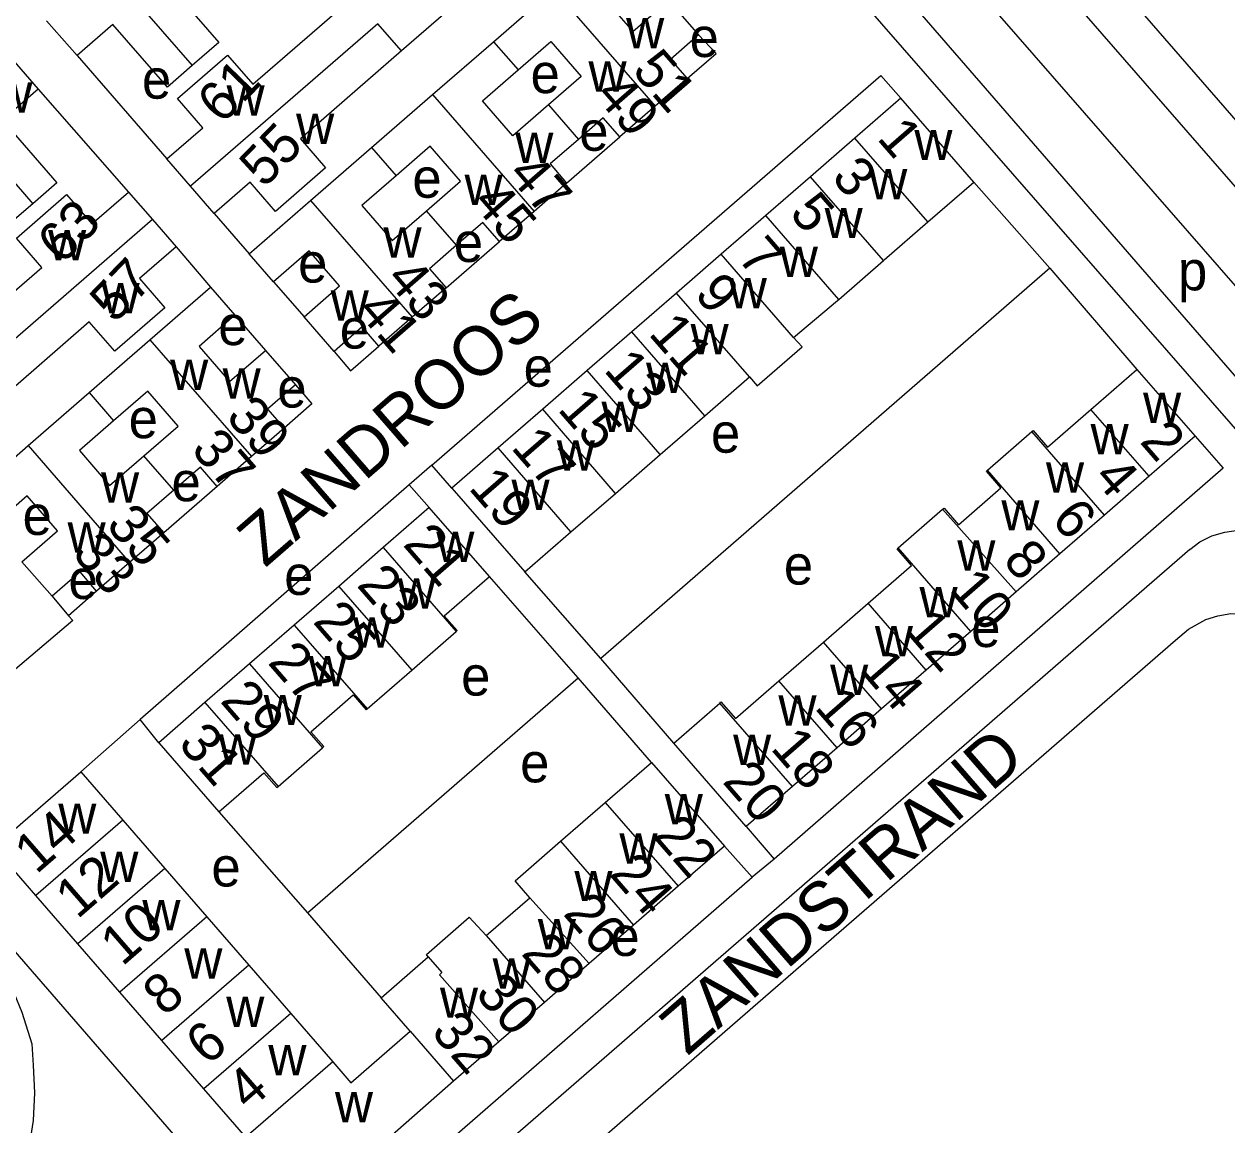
# Model space of a CAD drawing. Extents: x 155854 to 157362, y 383621 to 384685.
# Drawn here: x 156376.4 to 156498.5, y 383977 to 384088.8 of the extents above; entities that cross this region are included whole.
import ezdxf

# ---------------------------------------------------------------- set-up
doc = ezdxf.new("R2010")
doc.units = 0
for name, color, linetype in [('BLT_Basislijn', 7, 'Continuous'), ('BLT_Bebouwing', 7, 'Continuous'), ('BLT_Centroide', 7, 'Continuous'), ('BLT_Huisnummer', 7, 'Continuous'), ('BLT_Huisnummer_ tussenligend', 7, 'Continuous'), ('BLT_Onderverdeling_panden', 7, 'Continuous'), ('BLT_Straatnaam', 7, 'Continuous')]:
    doc.layers.add(name, color=color, linetype=linetype)

msp = doc.modelspace()

# ---------------------------------------------------------------- linework, layer by layer
at = {"layer": 'BLT_Basislijn'}
for p, q in [((156392.09, 384202.53), (156523.62, 384051.13)), ((156401.6, 384165.8), (156512.2, 384038.19)), ((156398.58, 384163.18), (156509.58, 384035.97)), ((156520.26, 384048.21), (156473.56, 384101.96)), ((156516.87, 384042.15), (156471.07, 384094.69)), ((156446.65, 384085.79), (156444.87, 384087.69)), ((156381.78, 384085.6), (156390.89, 384075.11)), ((156443.7, 384083.27), (156446.65, 384085.79)), ((156417.79, 384044.01), (156463.38, 384083.58)), ((156463.38, 384083.58), (156465.4, 384081.27)), ((156377.85, 384082.2), (156387.01, 384071.73)), ((156431.48, 384072.64), (156436.88, 384077.35)), ((156472.82, 384072.75), (156480.52, 384064)), ((156395.69, 384069.56), (156399.27, 384065.48)), ((156419.24, 384062.02), (156424.65, 384066.71)), ((156391.83, 384066.18), (156395.32, 384062.09)), ((156480.52, 384064), (156434.94, 384024.4)), ((156480.52, 384064), (156489.37, 384053.73)), ((156401.74, 384062.62), (156404.82, 384059.07)), ((156397.81, 384059.23), (156400.91, 384055.67)), ((156407.87, 384055.55), (156409.55, 384053.58)), ((156409.55, 384053.58), (156412.43, 384056.11)), ((156403.95, 384052.17), (156405.63, 384050.24)), ((156405.63, 384050.24), (156402.79, 384047.77)), ((156495.29, 384046.95), (156498.14, 384043.71)), ((156417.79, 384044.01), (156415.51, 384042.01)), ((156419.83, 384041.68), (156417.79, 384044.01)), ((156498.14, 384043.71), (156452.55, 384004.01)), ((156415.51, 384042.01), (156388.19, 384018.19)), ((156417.54, 384039.71), (156415.51, 384042.01)), ((156395.99, 384041.86), (156390.58, 384037.15)), ((156494.73, 384035.45), (156450.99, 383997.45)), ((156432.65, 384022.41), (156423.64, 384032.71)), ((156434.94, 384024.4), (156427.24, 384033.18)), ((156383.77, 384031.23), (156380.92, 384028.72)), ((156379.24, 384030.7), (156380.92, 384028.72)), ((156380.92, 384028.72), (156381.34, 384028.23)), ((156381.34, 384028.23), (156374.19, 384022.15)), ((156448.33, 383987.19), (156493.28, 384026.24)), ((156442.36, 384015.8), (156434.94, 384024.4)), ((156405.18, 383998.55), (156432.65, 384022.41)), ((156440.08, 384013.84), (156432.65, 384022.41)), ((156388.19, 384018.19), (156382.16, 384012.89)), ((156390.09, 384015.84), (156388.19, 384018.19)), ((156396.19, 384008.82), (156405.18, 383998.55)), ((156449.72, 384007.32), (156452.55, 384004.01)), ((156447.49, 384005.33), (156450.33, 384002.17)), ((156452.55, 384004.01), (156450.33, 384002.17)), ((156369.3, 384001.72), (156403.93, 383961.86)), ((156403.93, 383961.86), (156450.33, 384002.17)), ((156405.18, 383998.55), (156412.64, 383989.95)), ((156404.62, 383949.22), (156448.33, 383987.19))]:
    msp.add_line(p, q, dxfattribs=at)
for points in [[(156494.73, 384035.45), (156495.76, 384036.23), (156496.98, 384036.84), (156498.28, 384037.22), (156499.89, 384037.45), (156500.8, 384037.38), (156501.87, 384037.15), (156503.02, 384036.84), (156504.02, 384036.3), (156505.16, 384035.46), (156506.01, 384034.65), (156506.74, 384033.82)], [(156493.28, 384026.24), (156494.61, 384027.36), (156496.37, 384028.35), (156497.59, 384028.73), (156498.89, 384028.96), (156500.27, 384028.89), (156501.57, 384028.66), (156502.33, 384028.35), (156502.88, 384028.08)], [(156369.3, 384001.72), (156368.39, 383999.97), (156370.56, 383997.41), (156372.6, 383994.73), (156374.65, 383992.04), (156375.41, 383990.38), (156376.18, 383988.47), (156377.2, 383985.27), (156377.33, 383983.1), (156377.46, 383980.29), (156377.33, 383977.47), (156376.69, 383973.38), (156375.92, 383967.54), (156378.01, 383961.92)], [(156450.99, 383997.45), (156407.25, 383959.46), (156405.53, 383958.27)]]:
    msp.add_lwpolyline(points, dxfattribs=at)
at = {"layer": 'BLT_Bebouwing'}
for p, q in [((156424.06, 384087), (156430.17, 384092.31)), ((156441.83, 384091.18), (156444.87, 384087.69)), ((156381.78, 384085.6), (156378.69, 384089.13)), ((156417.87, 384081.63), (156424.06, 384087)), ((156426.55, 384084.14), (156429.87, 384087.03)), ((156374.77, 384085.74), (156377.85, 384082.2)), ((156443.7, 384083.27), (156440.47, 384080.46)), ((156411.68, 384076.26), (156417.87, 384081.63)), ((156465.4, 384081.27), (156460.74, 384077.22)), ((156472.82, 384072.75), (156465.4, 384081.27)), ((156440.47, 384080.46), (156436.88, 384077.35)), ((156405.49, 384070.88), (156411.68, 384076.26)), ((156417.64, 384076.39), (156414.17, 384073.39)), ((156460.74, 384077.22), (156456.23, 384073.3)), ((156393.3, 384072.32), (156390.89, 384075.11)), ((156431.48, 384072.64), (156428.17, 384069.77)), ((156456.23, 384073.3), (156451.69, 384069.36)), ((156387.01, 384071.73), (156389.43, 384068.95)), ((156395.69, 384069.56), (156393.3, 384072.32)), ((156399.27, 384065.48), (156405.49, 384070.88)), ((156389.43, 384068.95), (156391.83, 384066.18)), ((156428.17, 384069.77), (156424.65, 384066.71)), ((156451.69, 384069.36), (156447.16, 384065.42)), ((156463.73, 384064.86), (156468.16, 384068.7)), ((156401.74, 384062.62), (156399.27, 384065.48)), ((156447.16, 384065.42), (156442.63, 384061.49)), ((156459.1, 384060.84), (156463.64, 384064.78)), ((156463.64, 384064.78), (156463.73, 384064.86)), ((156389.18, 384056.75), (156395.32, 384062.09)), ((156395.32, 384062.09), (156397.81, 384059.23)), ((156419.24, 384062.02), (156415.79, 384059.03)), ((156442.63, 384061.49), (156438.1, 384057.56)), ((156454.5, 384056.97), (156458.98, 384060.73)), ((156458.98, 384060.73), (156459.1, 384060.84)), ((156407.87, 384055.55), (156404.82, 384059.07)), ((156415.79, 384059.03), (156412.43, 384056.11)), ((156383, 384051.38), (156389.18, 384056.75)), ((156438.1, 384057.56), (156433.58, 384053.62)), ((156400.91, 384055.67), (156403.95, 384052.17)), ((156433.58, 384053.62), (156429.05, 384049.69)), ((156484.71, 384049.68), (156489.37, 384053.73)), ((156489.37, 384053.73), (156495.29, 384046.95)), ((156445.5, 384049.03), (156450.04, 384052.97)), ((156376.81, 384046), (156383, 384051.38)), ((156388.96, 384051.53), (156385.48, 384048.52)), ((156429.05, 384049.69), (156424.52, 384045.76)), ((156440.97, 384045.1), (156445.5, 384049.03)), ((156402.79, 384047.77), (156399.48, 384044.89)), ((156474.2, 384043.49), (156478.72, 384047.42)), ((156478.72, 384047.42), (156478.84, 384047.53)), ((156495.29, 384046.95), (156490.61, 384042.88)), ((156370.62, 384040.61), (156376.81, 384046)), ((156424.52, 384045.76), (156419.83, 384041.68)), ((156399.48, 384044.89), (156395.99, 384041.86)), ((156436.45, 384041.15), (156440.97, 384045.1)), ((156474.09, 384043.4), (156474.2, 384043.49)), ((156490.61, 384042.88), (156486.09, 384038.95)), ((156419.83, 384041.68), (156427.24, 384033.18)), ((156431.91, 384037.23), (156436.45, 384041.15)), ((156417.54, 384039.71), (156412.87, 384035.65)), ((156423.64, 384032.71), (156417.54, 384039.71)), ((156469.65, 384039.53), (156469.79, 384039.66)), ((156465.15, 384035.62), (156469.65, 384039.53)), ((156486.09, 384038.95), (156481.56, 384035.01)), ((156390.58, 384037.15), (156387.12, 384034.14)), ((156427.24, 384033.18), (156431.91, 384037.23)), ((156412.87, 384035.65), (156408.35, 384031.71)), ((156465.04, 384035.52), (156465.15, 384035.62)), ((156481.56, 384035.01), (156477.13, 384031.16)), ((156379.24, 384030.7), (156376.19, 384034.21)), ((156387.12, 384034.14), (156383.77, 384031.23)), ((156408.35, 384031.71), (156403.82, 384027.78)), ((156477.13, 384031.16), (156472.51, 384027.14)), ((156457.55, 384026.05), (156462.08, 384029.99)), ((156403.82, 384027.78), (156399.3, 384023.84)), ((156415.76, 384023.2), (156420.28, 384027.14)), ((156420.28, 384027.14), (156420.37, 384027.22)), ((156472.51, 384027.14), (156467.98, 384023.2)), ((156453.02, 384022.12), (156457.55, 384026.05)), ((156399.3, 384023.84), (156394.77, 384019.91)), ((156411.24, 384019.27), (156415.76, 384023.2)), ((156467.98, 384023.2), (156463.45, 384019.26)), ((156394.77, 384019.91), (156390.09, 384015.84)), ((156411.13, 384019.18), (156411.24, 384019.27)), ((156442.36, 384015.8), (156447.03, 384019.86)), ((156447.03, 384019.86), (156447.15, 384019.97)), ((156463.45, 384019.26), (156458.93, 384015.33)), ((156390.09, 384015.84), (156396.19, 384008.82)), ((156449.72, 384007.32), (156442.36, 384015.8)), ((156458.93, 384015.33), (156454.4, 384011.39)), ((156373.34, 384005.22), (156382.16, 384012.89)), ((156382.16, 384012.89), (156386.42, 384007.98)), ((156435.4, 384009.77), (156440.08, 384013.84)), ((156440.08, 384013.84), (156447.49, 384005.33)), ((156454.4, 384011.39), (156449.72, 384007.32)), ((156430.87, 384005.84), (156435.4, 384009.77)), ((156386.42, 384007.98), (156390.68, 384003.08)), ((156377.6, 384000.32), (156373.34, 384005.22)), ((156447.49, 384005.33), (156442.8, 384001.27)), ((156390.68, 384003.08), (156394.95, 383998.17)), ((156442.8, 384001.27), (156438.28, 383997.33)), ((156381.86, 383995.41), (156377.6, 384000.32)), ((156423.32, 383996.26), (156427.73, 384000.09)), ((156394.95, 383998.17), (156399.21, 383993.26)), ((156438.28, 383997.33), (156433.76, 383993.41)), ((156386.12, 383990.5), (156381.86, 383995.41)), ((156399.21, 383993.26), (156403.47, 383988.35)), ((156433.76, 383993.41), (156429.22, 383989.46)), ((156390.39, 383985.6), (156386.12, 383990.5)), ((156415.6, 383986.54), (156412.64, 383989.95)), ((156403.47, 383988.35), (156407.74, 383983.45)), ((156429.22, 383989.46), (156424.61, 383985.46)), ((156394.65, 383980.69), (156390.39, 383985.6)), ((156424.61, 383985.46), (156420.01, 383981.46)), ((156398.91, 383975.78), (156394.65, 383980.69))]:
    msp.add_line(p, q, dxfattribs=at)
for points in [[(156432.72, 384101.7), (156429.08, 384098.54), (156431.64, 384095.59), (156426.56, 384091.18), (156424, 384094.12), (156414.72, 384086.06)], [(156394.2, 384096.38), (156390.65, 384093.3), (156396.19, 384086.93), (156393.48, 384084.58)], [(156438.74, 384094.73), (156435.12, 384091.59), (156438.21, 384088.04), (156441.83, 384091.18)], [(156390.89, 384075.11), (156394.56, 384078.26), (156391.98, 384081.23), (156397.07, 384085.64), (156399.63, 384082.69), (156409.9, 384091.61)], [(156393.48, 384084.58), (156390.96, 384082.38), (156385.41, 384088.76), (156381.78, 384085.6)], [(156444.87, 384087.69), (156442.02, 384085.21), (156443.7, 384083.27)], [(156414.72, 384086.06), (156404.45, 384077.14), (156407.01, 384074.21), (156401.93, 384069.77), (156399.36, 384072.73), (156395.69, 384069.56)], [(156429.87, 384087.03), (156432.96, 384083.48), (156429.63, 384080.59)], [(156429.63, 384080.59), (156426.01, 384077.44), (156422.93, 384080.99), (156426.55, 384084.14)], [(156377.85, 384082.2), (156374.22, 384079.05), (156379.74, 384072.68), (156377.29, 384070.55)], [(156436.88, 384077.35), (156435.2, 384079.29), (156432.67, 384077.08)], [(156417.26, 384069.84), (156420.72, 384072.84), (156417.64, 384076.39)], [(156432.67, 384077.08), (156429.8, 384074.59), (156431.48, 384072.64)], [(156414.17, 384073.39), (156410.69, 384070.36), (156413.77, 384066.81), (156417.26, 384069.84)], [(156468.16, 384068.7), (156472.82, 384072.75)], [(156377.29, 384070.55), (156374.5, 384068.14), (156371.44, 384071.66), (156367.96, 384068.65)], [(156368.27, 384055.48), (156378.21, 384064.09), (156375.63, 384067.07), (156380.72, 384071.48), (156383.29, 384068.5), (156387.01, 384071.73)], [(156424.65, 384066.71), (156422.97, 384068.66), (156420.3, 384066.34)], [(156391.83, 384066.18), (156388.11, 384062.96), (156390.69, 384059.99), (156385.61, 384055.57), (156383.02, 384058.55), (156373.09, 384049.92), (156370.7, 384052.68)], [(156404.82, 384059.07), (156408.43, 384062.21), (156405.35, 384065.76), (156401.74, 384062.62)], [(156420.3, 384066.34), (156417.55, 384063.96), (156419.24, 384062.02)], [(156397.81, 384059.23), (156394.18, 384056.07), (156397.27, 384052.51), (156400.91, 384055.67)], [(156412.43, 384056.11), (156410.74, 384058.05), (156407.87, 384055.55)], [(156450.04, 384052.97), (156450.81, 384052.07), (156455.38, 384056.04), (156454.5, 384056.97)], [(156403.95, 384052.17), (156401.11, 384049.7), (156402.79, 384047.77)], [(156388.56, 384044.97), (156392.03, 384047.98), (156388.96, 384051.53)], [(156478.84, 384047.53), (156480.31, 384045.85), (156484.71, 384049.68)], [(156385.48, 384048.52), (156382.02, 384045.51), (156385.09, 384041.96), (156388.56, 384044.97)], [(156395.99, 384041.86), (156394.31, 384043.8), (156391.61, 384041.46)], [(156469.79, 384039.66), (156471.25, 384037.97), (156475.55, 384041.71), (156474.09, 384043.4)], [(156376.19, 384034.21), (156379.8, 384037.35), (156376.72, 384040.9), (156373.11, 384037.76)], [(156391.61, 384041.46), (156388.88, 384039.09), (156390.58, 384037.15)], [(156462.08, 384029.99), (156466.5, 384033.84), (156465.04, 384035.52)], [(156383.77, 384031.23), (156382.09, 384033.17), (156379.24, 384030.7)], [(156420.37, 384027.22), (156419.06, 384028.73), (156423.64, 384032.71)], [(156447.15, 384019.97), (156448.62, 384018.29), (156453.02, 384022.12)], [(156405.52, 384016.95), (156409.82, 384020.69), (156411.13, 384019.18)], [(156406.71, 384015.33), (156406.84, 384015.44), (156405.52, 384016.95)], [(156402.19, 384011.39), (156406.71, 384015.33)], [(156396.19, 384008.82), (156400.74, 384012.78), (156402.05, 384011.28)], [(156402.05, 384011.28), (156402.19, 384011.39)], [(156427.73, 384000.09), (156426.24, 384001.81), (156430.87, 384005.84)], [(156417.43, 383994.11), (156417.25, 383994.32), (156421.6, 383998.11), (156423.32, 383996.26)], [(156412.64, 383989.95), (156417.43, 383994.11)], [(156407.74, 383983.45), (156409.59, 383981.31), (156415.6, 383986.54)], [(156420.01, 383981.46), (156411.81, 383974.27), (156412.21, 383973.69), (156405.71, 383968.07), (156398.91, 383975.78)]]:
    msp.add_lwpolyline(points, dxfattribs=at)
at = {"layer": 'BLT_Onderverdeling_panden'}
for p, q in [((156383.18, 384096.43), (156393.48, 384084.58)), ((156430.17, 384092.31), (156440.47, 384080.46)), ((156412.31, 384088.83), (156393.3, 384072.32)), ((156414.72, 384086.06), (156412.31, 384088.83)), ((156424.06, 384087), (156426.55, 384084.14)), ((156367.01, 384082.4), (156377.29, 384070.55)), ((156417.87, 384081.63), (156428.17, 384069.77)), ((156429.63, 384080.59), (156432.67, 384077.08)), ((156411.68, 384076.26), (156414.17, 384073.39)), ((156468.16, 384068.7), (156460.74, 384077.22)), ((156463.64, 384064.78), (156456.23, 384073.3)), ((156405.49, 384070.88), (156415.79, 384059.03)), ((156389.43, 384068.95), (156370.7, 384052.68)), ((156420.3, 384066.34), (156417.26, 384069.84)), ((156459.1, 384060.84), (156451.69, 384069.36)), ((156454.5, 384056.97), (156447.16, 384065.42)), ((156450.04, 384052.97), (156442.63, 384061.49)), ((156389.18, 384056.75), (156399.48, 384044.89)), ((156445.5, 384049.03), (156438.1, 384057.56)), ((156440.97, 384045.1), (156433.58, 384053.62)), ((156383, 384051.38), (156385.48, 384048.52)), ((156436.45, 384041.15), (156429.05, 384049.69)), ((156490.61, 384042.88), (156484.71, 384049.68)), ((156486.09, 384038.95), (156478.72, 384047.42)), ((156376.81, 384046), (156387.12, 384034.14)), ((156431.91, 384037.23), (156424.52, 384045.76)), ((156391.61, 384041.46), (156388.56, 384044.97)), ((156481.56, 384035.01), (156474.2, 384043.49)), ((156477.13, 384031.16), (156469.65, 384039.53)), ((156412.87, 384035.65), (156420.28, 384027.14)), ((156472.51, 384027.14), (156465.15, 384035.62)), ((156408.35, 384031.71), (156415.76, 384023.2)), ((156467.98, 384023.2), (156462.08, 384029.99)), ((156403.82, 384027.78), (156411.24, 384019.27)), ((156463.45, 384019.26), (156457.55, 384026.05)), ((156399.3, 384023.84), (156406.71, 384015.33)), ((156458.93, 384015.33), (156453.02, 384022.12)), ((156394.77, 384019.91), (156402.19, 384011.39)), ((156454.4, 384011.39), (156447.03, 384019.86)), ((156435.4, 384009.77), (156442.8, 384001.27)), ((156386.42, 384007.98), (156377.6, 384000.32)), ((156430.87, 384005.84), (156438.28, 383997.33)), ((156390.68, 384003.08), (156381.86, 383995.41)), ((156427.73, 384000.09), (156433.76, 383993.41)), ((156394.95, 383998.17), (156386.12, 383990.5)), ((156423.32, 383996.26), (156429.22, 383989.46)), ((156399.21, 383993.26), (156390.39, 383985.6)), ((156403.47, 383988.35), (156394.65, 383980.69)), ((156415.6, 383986.54), (156420.01, 383981.46)), ((156407.74, 383983.45), (156398.91, 383975.78))]:
    msp.add_line(p, q, dxfattribs=at)
msp.add_lwpolyline([(156417.43, 383994.11), (156418.82, 383992.51), (156418.59, 383992.27), (156424.61, 383985.46)], dxfattribs=at)

# ---------------------------------------------------------------- texts
at = {"layer": 'BLT_Centroide'}
for s, p in [('w', (156437.52, 384086.33)), ('e', (156443.96, 384085.45)), ('e', (156427.82, 384081.78)), ('w', (156433.7, 384081.93)), ('e', (156388.37, 384081.22)), ('w', (156373.38, 384079.8)), ('w', (156396.96, 384079.51)), ('w', (156404.02, 384076.61)), ('e', (156432.76, 384075.93)), ('w', (156426.27, 384074.7)), ('w', (156466.78, 384074.98)), ('e', (156415.82, 384071.16)), ('w', (156462.19, 384071)), ('w', (156421.12, 384070.43)), ('w', (156457.67, 384067.06)), ('w', (156378.84, 384064.8)), ('w', (156412.89, 384065.09)), ('e', (156420.03, 384064.64)), ('e', (156404.22, 384062.55)), ('w', (156453.12, 384063.12)), ('p', (156493.54, 384061.76)), ('w', (156447.94, 384059.95)), ('w', (156384.27, 384059.44)), ('w', (156407.53, 384058.69)), ('e', (156396.12, 384056.2)), ('e', (156408.45, 384055.85)), ('w', (156444.06, 384055.27)), ('w', (156391.23, 384051.64)), ('e', (156427.11, 384051.98)), ('w', (156439.55, 384051.33)), ('w', (156396.56, 384050.78)), ('e', (156402.11, 384049.86)), ('w', (156490, 384048.3)), ('e', (156387.02, 384046.75)), ('w', (156435.02, 384047.39)), ('e', (156446.13, 384045.28)), ('w', (156484.67, 384045.11)), ('w', (156430.48, 384043.45)), ('w', (156384.22, 384040.22)), ('e', (156391.37, 384040.35)), ('w', (156480.14, 384041.22)), ('w', (156425.88, 384039.47)), ('e', (156376.25, 384036.93)), ('w', (156475.61, 384037.38)), ('w', (156380.82, 384035.14)), ('w', (156418.25, 384034.19)), ('w', (156471.14, 384033.3)), ('e', (156453.53, 384031.89)), ('e', (156380.91, 384030.43)), ('e', (156402.81, 384030.84)), ('w', (156414.31, 384029.44)), ('w', (156467.3, 384028.58)), ('e', (156472.55, 384025.55)), ('w', (156409.8, 384025.5)), ('w', (156462.77, 384024.62)), ('w', (156405.27, 384021.56)), ('e', (156420.77, 384020.62)), ('w', (156458.23, 384020.69)), ('w', (156400.73, 384017.62)), ('w', (156452.98, 384017.56)), ('w', (156396.14, 384013.61)), ('w', (156448.38, 384013.59)), ('e', (156426.76, 384011.81)), ('w', (156441.44, 384007.56)), ('w', (156379.88, 384006.59)), ('w', (156436.84, 384003.56)), ('w', (156384.14, 384001.69)), ('e', (156395.42, 384001.24)), ('w', (156432.27, 383999.75)), ('w', (156388.41, 383996.78)), ('w', (156428.56, 383994.86)), ('e', (156435.92, 383994.19)), ('w', (156392.67, 383991.88)), ('w', (156423.97, 383990.86)), ('w', (156418.62, 383987.91)), ('w', (156396.93, 383986.97)), ('w', (156401.2, 383982.06)), ('w', (156407.96, 383977.31))]:
    msp.add_text(s, height=4, dxfattribs=at).set_placement(p)
at = {"layer": 'BLT_Huisnummer'}
for s, rotation, p in [('51', 310.9842, (156438.02, 384084.01)), ('61', 45.9095, (156396.51, 384078.52)), ('55', 45.9095, (156400.78, 384072.05)), ('1', 310.9842, (156462.89, 384077.16)), ('47', 310.9842, (156425.37, 384073.45)), ('63', 45.9095, (156380.28, 384064.27)), ('7', 310.9842, (156448.71, 384065.02)), ('57', 45.9095, (156385.59, 384058.31)), ('41', 310.9842, (156410.09, 384059.61)), ('13', 310.9842, (156435.16, 384053.63)), ('39', 310.9842, (156396.78, 384048.85)), ('2', 310.9811, (156489.57, 384046.37)), ('19', 310.9842, (156421.43, 384041.66)), ('21', 310.9842, (156414.77, 384035.93)), ('33', 310.9842, (156381.17, 384035.02)), ('8', 310.9811, (156475.65, 384034.27)), ('27', 310.9842, (156401.05, 384023.94)), ('14', 310.9811, (156461.12, 384023.23)), ('31', 310.9842, (156391.94, 384015.67)), ('20', 310.9811, (156447.21, 384011.85)), ('14', 40.9824, (156377.64, 384002.41)), ('22', 310.9811, (156440.14, 384006.33)), ('26', 310.9811, (156431.03, 383998.44)), ('8', 40.9824, (156390.68, 383987.96)), ('32', 310.9811, (156417.61, 383986.4))]:
    msp.add_text(s, height=4, rotation=rotation, dxfattribs=at).set_placement(p)
at = {"layer": 'BLT_Huisnummer_ tussenligend'}
for s, rotation, p in [('49', 310.9842, (156434.25, 384081.51)), ('3', 310.9842, (156458.26, 384073.16)), ('45', 310.9842, (156421.8, 384070.61)), ('5', 310.9842, (156453.99, 384069.52)), ('43', 310.9842, (156413.01, 384062.84)), ('9', 310.9842, (156444.34, 384061.32)), ('11', 310.9842, (156439.7, 384057.32)), ('15', 310.9842, (156430.47, 384049.65)), ('37', 310.9842, (156393.24, 384045.54)), ('17', 310.9842, (156425.74, 384045.77)), ('4', 310.9811, (156484.84, 384042.68)), ('35', 310.9842, (156384.61, 384037.87)), ('6', 310.9811, (156480.57, 384038.43)), ('23', 310.9842, (156410.08, 384031.8)), ('10', 310.9811, (156470.23, 384031.35)), ('25', 310.9842, (156405.63, 384028.09)), ('12', 310.9811, (156465.7, 384027.25)), ('29', 310.9842, (156396.22, 384020.04)), ('16', 310.9811, (156456.56, 384019.37)), ('18', 310.9811, (156452.09, 384015.24)), ('12', 40.9824, (156381.81, 383997.85)), ('24', 310.9811, (156435.73, 384002.46)), ('10', 40.9824, (156386.37, 383993.06)), ('28', 310.9811, (156426.78, 383994.4)), ('30', 310.9811, (156422.09, 383990.28)), ('6', 40.9824, (156395.04, 383982.97)), ('4', 40.9824, (156399.19, 383978.39))]:
    msp.add_text(s, height=4, rotation=rotation, dxfattribs=at).set_placement(p)
at = {"layer": 'BLT_Straatnaam'}
for s, p in [('ZANDROOS', (156358.59, 384081.38)), ('ZANDROOS', (156400.87, 384033.54)), ('ZANDSTRAND', (156443.74, 383983.98))]:
    msp.add_text(s, height=5, rotation=40.9822, dxfattribs=at).set_placement(p)

doc.saveas('drawing.dxf')
